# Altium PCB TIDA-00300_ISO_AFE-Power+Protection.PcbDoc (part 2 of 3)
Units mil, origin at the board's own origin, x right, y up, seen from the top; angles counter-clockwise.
Board outline 3622.05 x 2204.8 mil, 4 copper layers (Top Layer, GND Layer, PWR Layer, Bottom Layer), stack 63.6 mil thick; 240 components, 107 nets, 584 pads, 225 vias.
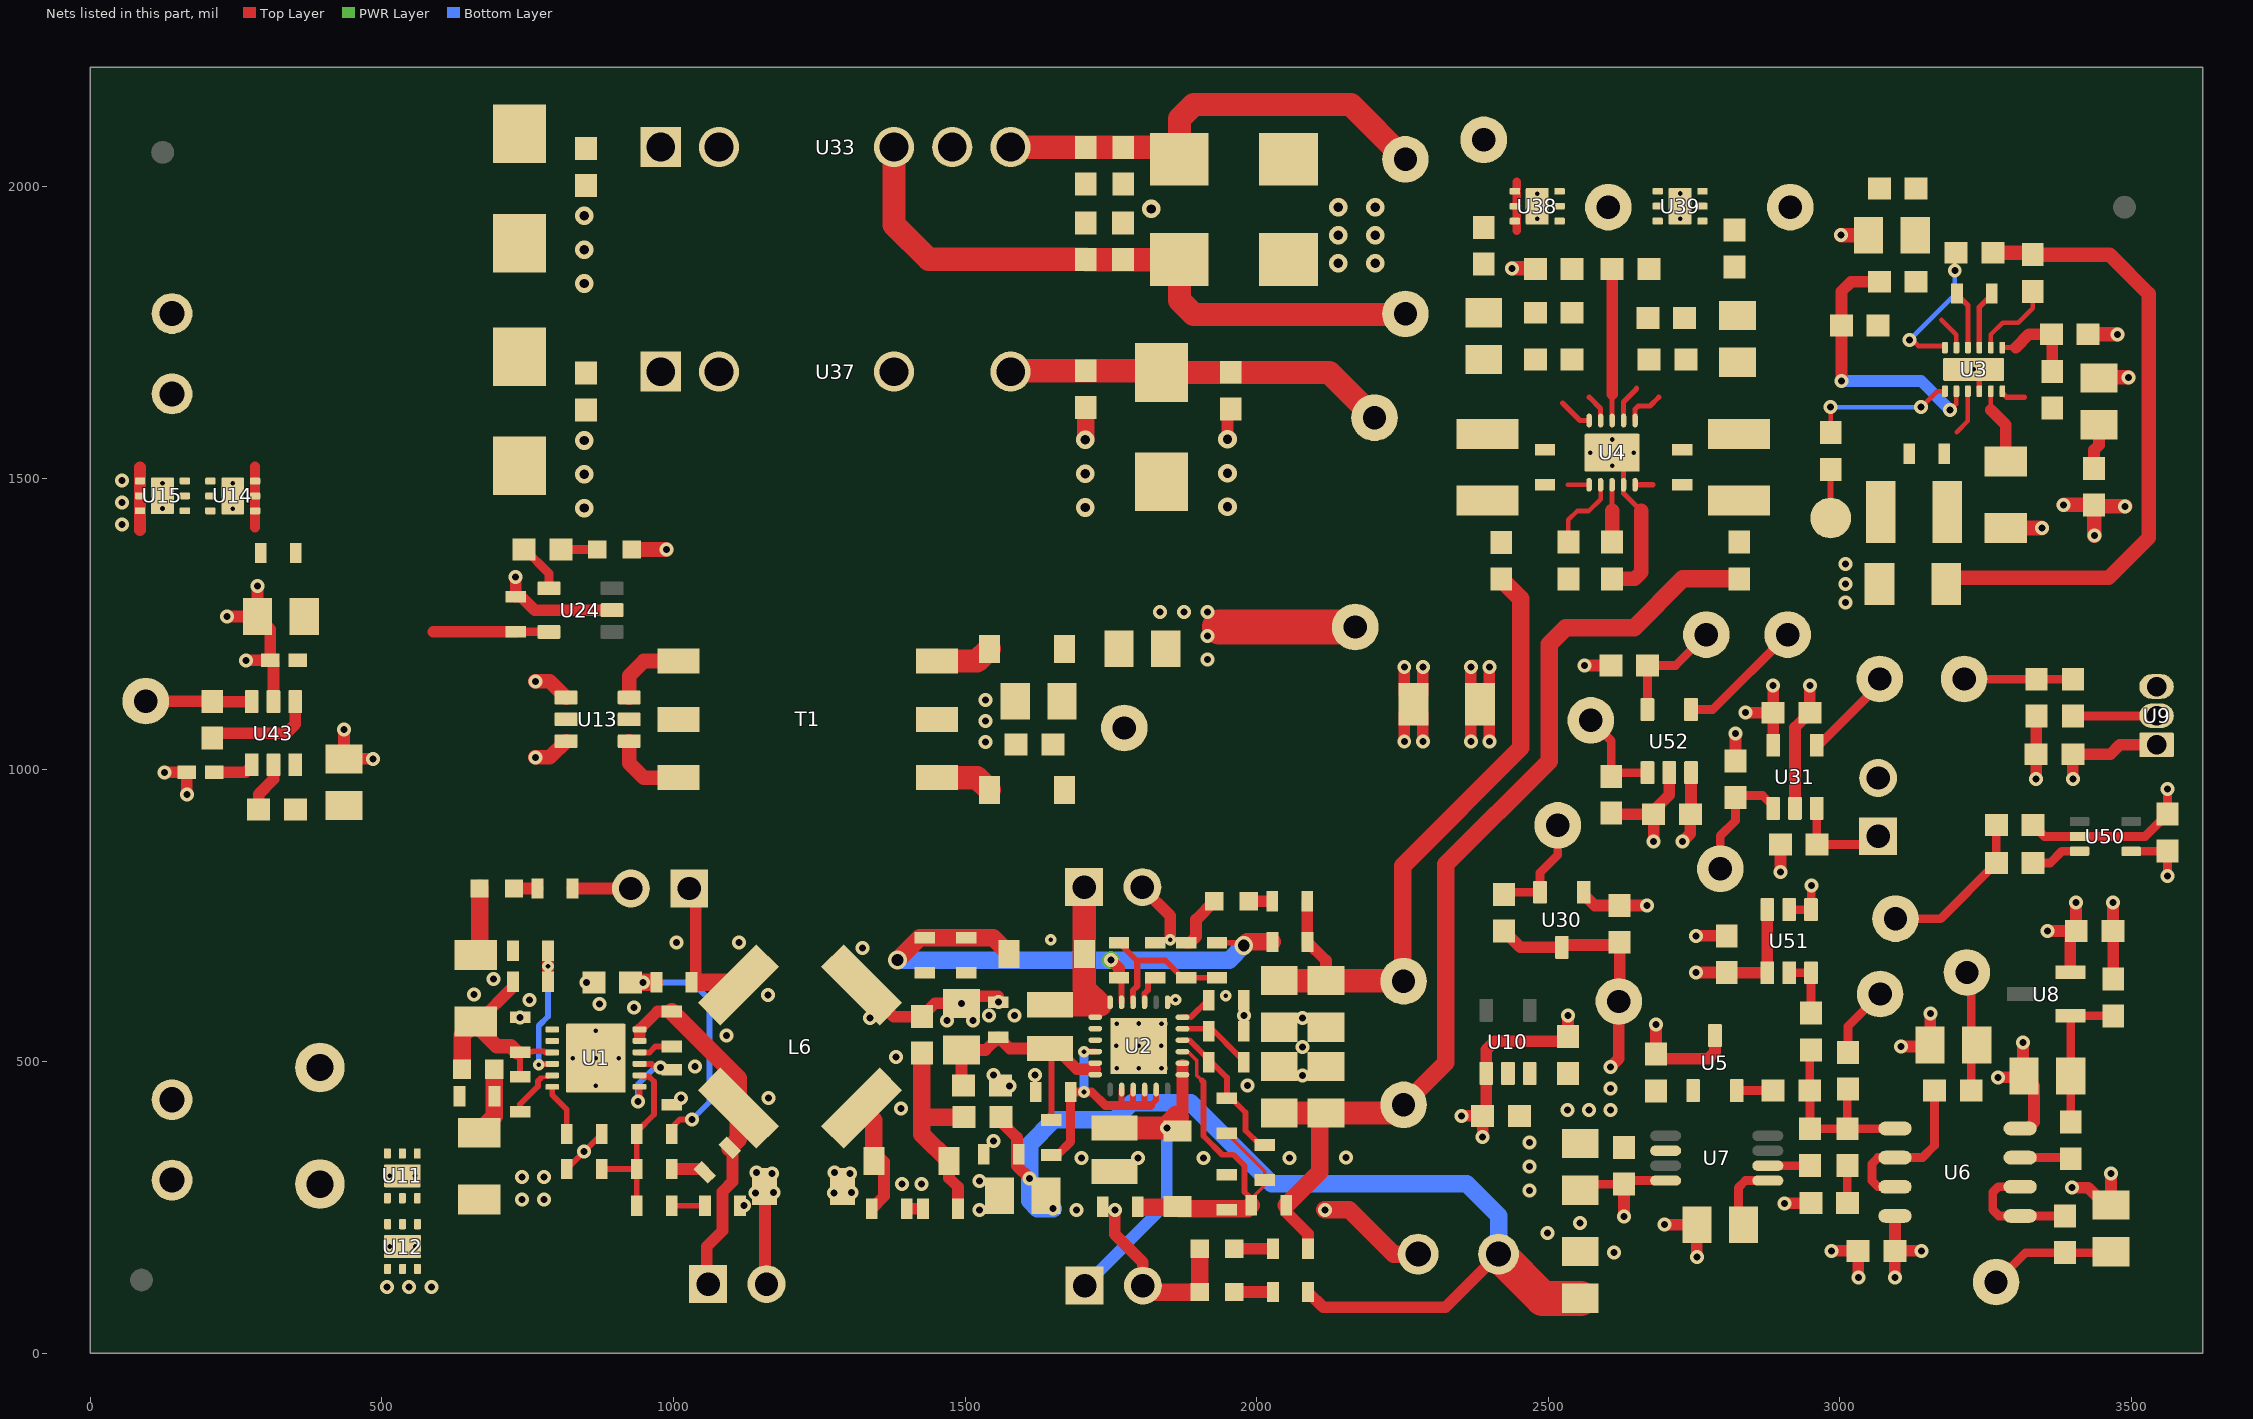
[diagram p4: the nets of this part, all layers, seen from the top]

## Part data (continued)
L4 L5: "Inductor, Wirewound, Ferrite, 10 µH, 0.47 A, 0.435 ohm, SMD", Manufacturer="Wurth Elektronik", Supplier Part Number 1=732-5428-1-ND, Value1="0.435 ohm", Value2=0.47A, ValueDisplayed=10µH
L6: "Coupled inductor, 22 µH, 1.1 A, 0.48 ohm, SMD", Manufacturer="Wurth Elektronik", Supplier Part Number 1=732-2598-1-ND, ValueDisplayed=22µH
Logo1: library part CMP-0074769-1
Logo2: library part Pb-Free
Logo3: library part FCC_disclaimer, "FCC_disclaimer"
Logo4: library part ESD_Susceptible, "ESD Susceptible Symbol"
PT1: library part POLYSWITCH_RXE135, "PTC THERMISTOR C 830-A 160-A 70", Manufacturer=Raychem, Supplier Part Number 1=495-76377-ND
R1: "RES, 1.21 k, 1%, 0.1 W, 0603", Manufacturer=Vishay-Dale, Power_W=0.1, Supplier Part Number 1=541-1.21KHCT-ND, TempCo="100 ppm/C", Tolerance_%=1, Value1=1%, Value2=0.1W, Value_Code=1k21, ValueDisplayed=1.21k
R2 R22 R23 R52: "RES, 1.00, 1%, 0.1 W, 0603", Manufacturer=Vishay-Dale, Power_W=0.1, Supplier Part Number 1=541-3956-1-ND, TempCo="100 ppm/C", Tolerance_%=1, Value1=1%, Value2=0.1W, Value_Code=1R00, ValueDisplayed=1.00
R3: "RES, 113 k, 1%, 0.1 W, 0603", Manufacturer=Vishay-Dale, Power_W=0.1, Supplier Part Number 1=541-113KHCT-ND, TempCo="100 ppm/C", Tolerance_%=1, Value1=1%, Value2=0.1W, Value_Code=113k
R4: "RES, 16.9 k, 1%, 0.1 W, 0603", Manufacturer=Vishay-Dale, Power_W=0.1, Supplier Part Number 1=541-16.9KHCT-ND, TempCo="100 ppm/C", Tolerance_%=1, Value1=1%, Value2=0.1W, Value_Code=16k9, ValueDisplayed=16.9k
R5: "RES, 27.4 k, 1%, 0.1 W, 0603", Manufacturer=Vishay-Dale, Power_W=0.1, Supplier Part Number 1=541-27.4KHCT-ND, TempCo="100 ppm/C", Tolerance_%=1, Value1=1%, Value2=0.1W, Value_Code=27k4, ValueDisplayed=27.4k
R7: "RES, 3.48 k, 1%, 0.1 W, 0603", Manufacturer=Vishay-Dale, Power_W=0.1, Supplier Part Number 1=541-3.48KHCT-ND, TempCo="100 ppm/C", Tolerance_%=1, Value1=1%, Value2=0.1W, Value_Code=3k48, ValueDisplayed=3.48k
R8 R14 R21: "RES, 5.36 k, 1%, 0.1 W, 0603", Manufacturer=Vishay-Dale, Power_W=0.1, Supplier Part Number 1=541-5.36KHCT-ND, TempCo="100 ppm/C", Tolerance_%=1, Value1=1%, Value2=0.1W, Value_Code=5k36, ValueDisplayed=5.36k
R9: "RES, 150, 1%, 0.1 W, 0603", Manufacturer=Vishay-Dale, Power_W=0.1, Supplier Part Number 1=541-150HCT-ND, TempCo="100 ppm/C", Tolerance_%=1, Value1=1%, Value2=0.1W, Value_Code=150R, ValueDisplayed=150
R10 R13: "RES, 2.00 k, 1%, 0.1 W, 0603", Manufacturer=Vishay-Dale, Power_W=0.1, Supplier Part Number 1=541-2.00KHCT-ND, TempCo="100 ppm/C", Tolerance_%=1, Value1=1%, Value2=0.1W, Value_Code=2k00, ValueDisplayed=2.00k
R11: "RES, 42.2, 1%, 0.1 W, 0603", Manufacturer=Vishay-Dale, Power_W=0.1, Supplier Part Number 1=541-42.2HCT-ND, TempCo="100 ppm/C", Tolerance_%=1, Value1=1%, Value2=0.1W, Value_Code=42R2, ValueDisplayed=42.2
R12 R103 R104: "RES, 0, 5%, 0.1 W, 0603", Manufacturer=Panasonic, Power_W=0.1, Supplier Part Number 1=P0.0GCT-ND, TempCo="600 ppm/C", Tolerance_%=5, Value1=5%, Value2=0.1W, Value_Code=0000, ValueDisplayed=0
R15: "RES, 976 k, 1%, 0.1 W, 0603", Manufacturer=Vishay-Dale, Power_W=0.1, Supplier Part Number 1=541-976KHCT-ND, TempCo="100 ppm/C", Tolerance_%=1, Value1=1%, Value2=0.1W, Value_Code=976k
R16: "RES, 86.6 k, 1%, 0.1 W, 0603", Manufacturer=Vishay-Dale, Power_W=0.1, Supplier Part Number 1=541-86.6KHCT-ND, TempCo="100 ppm/C", Tolerance_%=1, Value1=1%, Value2=0.1W, Value_Code=86k6, ValueDisplayed=86.6k
R17: "RES, 105 k, 1%, 0.1 W, 0603", Manufacturer=Vishay-Dale, Power_W=0.1, Supplier Part Number 1=541-105KHCT-ND, TempCo="100 ppm/C", Tolerance_%=1, Value1=1%, Value2=0.1W, Value_Code=105k
R18: "RES, 1.30 M, 1%, 0.1 W, 0603", Manufacturer=Vishay-Dale, Power_W=0.1, Supplier Part Number 1=541-1.30MHCT-ND, TempCo="100 ppm/C", Tolerance_%=1, Value1=1%, Value2=0.1W, Value_Code=1M30, ValueDisplayed=1.30M
R19: "RES, 0, 5%, 0.25 W, 1206", Manufacturer=Vishay-Dale, Power_W=0.25, Supplier Part Number 1=541-0.0ECT-ND, TempCo="200 ppm/C", Tolerance_%=5, Value1=5%, Value2=0.25W, Value_Code=0000, ValueDisplayed=0
R20 R44 R45 R47 R50 R117: "RES, 100, 1%, 0.1 W, 0603", Manufacturer=Vishay-Dale, Power_W=0.1, Supplier Part Number 1=541-100HCT-ND, TempCo="100 ppm/C", Tolerance_%=1, Value1=1%, Value2=0.1W, Value_Code=100R, ValueDisplayed=100
R24 R25 R26 R31 R33 R36 R38 R40 R41: "RES, 0, 5%, 0.1 W, 0603", Manufacturer=Vishay-Dale, Power_W=0.1, Supplier Part Number 1=541-0.0GCT-ND, TempCo="200 ppm/C", Tolerance_%=5, Value1=5%, Value2=0.1W, Value_Code=0000, ValueDisplayed=0
R27 R28 R30 R34: "RES, 249 k, 1%, 0.1 W, 0603", Manufacturer=Vishay-Dale, Power_W=0.1, Supplier Part Number 1=541-249KHCT-ND, TempCo="100 ppm/C", Tolerance_%=1, Value1=1%, Value2=0.1W, Value_Code=249k
R29: library part RNCF0603TKY10K0, "RES, 10.0k ohm, 1%, 0.1W, 0603", Manufacturer="Stackpole Electronics Inc", Power_W=0.063, Supplier Part Number 1=541-10.0KHCT-ND, TempCo="5 ppm/C", Tolerance_%=0.01, Value1=0.01%, Value2=0.063W, Value_Code=10k0
R32 R37: "RES, 75.0 k, 1%, 0.1 W, 0603", Manufacturer=Vishay-Dale, Power_W=0.1, Supplier Part Number 1=541-75.0KHCT-ND, TempCo="100 ppm/C", Tolerance_%=1, Value1=1%, Value2=0.1W, Value_Code=75k0, ValueDisplayed=75.0k
R35: "RES, 27.0 k, 1%, 0.1 W, 0603", Manufacturer="Yageo America", Power_W=0.1, Supplier Part Number 1=311-27.0KHRCT-ND, TempCo="200 ppm/C", Tolerance_%=1, Value1=1%, Value2=0.1W, Value_Code=27k0, ValueDisplayed=27.0k
R39: "RES, 24.0 k, 1%, 0.1 W, 0603", Manufacturer="Yageo America", Power_W=0.1, Supplier Part Number 1=311-24.0KHRCT-ND, TempCo="200 ppm/C", Tolerance_%=1, Value1=1%, Value2=0.1W, Value_Code=24k0, ValueDisplayed=24.0k
R42 R43 R48 R49 R118: "RES, 0 ohm, 5%, 0.1W, 0603", Manufacturer=Vishay-Dale, Power_W=0.1, Supplier Part Number 1=541-0.0GCT-ND, TempCo="200 ppm/C", Tolerance_%=5, Value1=5%, Value2=0.1W, Value_Code=0000
R46: "RES, 2.55 k, 1%, 0.1 W, 0603", Manufacturer=Vishay-Dale, Power_W=0.1, Supplier Part Number 1=541-2.55KHCT-ND, TempCo="100 ppm/C", Tolerance_%=1, Value1=1%, Value2=0.1W, Value_Code=2k55, ValueDisplayed=2.55k
R51: "RES, 0, 5%, 0.25 W, 1206", Manufacturer="Yageo America", Power_W=0.25, Supplier Part Number 1=311-0.0ERCT-ND, TempCo="200 ppm/C", Tolerance_%=5, Value1=5%, Value2=0.25W, Value_Code=0000, ValueDisplayed=0
R75: "RES, 1.00 k, 1%, 0.1 W, AEC-Q200 Grade 0, 0603", Manufacturer=Panasonic, Power_W=0.1, Supplier Part Number 1=P1.00KHCT-ND, TempCo="100 ppm/C", Tolerance_%=1, Value1=1%, Value2=0.1W, Value_Code=1k00, ValueDisplayed=1.00k
R86 R87 R94 R114 R115 R119: "RES, 10.0 k, 1%, 0.1 W, 0603", Manufacturer="Yageo America", Power_W=0.1, Supplier Part Number 1=311-10.0KHRCT-ND, TempCo="200 ppm/C", Tolerance_%=1, Value1=1%, Value2=0.1W, Value_Code=10k0, ValueDisplayed=10.0k
R112 R113: "RES, 0, 5%, 0.125 W, 0805", Manufacturer=Panasonic, Power_W=0.125, Supplier Part Number 1=P0.0ACT-ND, TempCo="600 ppm/C", Tolerance_%=5, Value1=5%, Value2=0.125W, Value_Code=0000, ValueDisplayed=0
R116: "RES, 1.00 k, 1%, 0.1 W, 0603", Manufacturer=Vishay-Dale, Power_W=0.1, Supplier Part Number 1=541-1.00KHCT-ND, TempCo="100 ppm/C", Tolerance_%=1, Value1=1%, Value2=0.1W, Value_Code=1k00, ValueDisplayed=1.00k
T1: library part CMP-0030623-1, "Transformer, 105uH, TH", Manufacturer="Wurth Elektronik", Supplier Part Number 1=1297-1178-1-ND, ValueDisplayed=105uH
TP1 TP2 TP5 TP6 TP24 TP25 TP27 TP29 TP31 TP43 TP44 TP49: "Test Point, Miniature, Red, TH", Color=Red, Manufacturer=Keystone, Supplier Part Number 1=36-5000-ND
TP3: library part PogoPad, "Pad for Pogo Pin Connector"
TP4 TP7 TP9 TP10 TP33 TP38 TP45 TP46 TP47 TP48: "Test Point, Miniature, White, TH", Color=White, Manufacturer=Keystone, Supplier Part Number 1=36-5002-ND
TP32: "Test Point, Miniature, Black, TH", Color=Black, Manufacturer=Keystone, Supplier Part Number 1=36-5001-ND
U1: "Wide Input 65V, 1.5A Synchronous Step-Down DC-DC Converter, DNT0012B", Alternate Manufacturer="Texas Instruments", Alternate PartNumber=LM5160DNTT, Supplier Part Number 1=296-46122-1-ND
U2: "Positive and Negative Output DC-DC Converter, RGE0024B", Alternate Manufacturer="Texas Instruments", Alternate PartNumber=TPS65130RGET, Supplier Part Number 1=296-17080-1-ND
U3: library part LM27762DSSR, "Low-Noise Regulated Switched-Capacitor Voltage Inverter and Positive LDO, DSS0012B", Alternate Manufacturer="Texas Instruments", Supplier Part Number 1=296-44944-1-ND
U4: "Wide-VIN (±33 V), 150-mA, Spilt-Rail Output, Positive and Negative LDO Voltage Regulator with Startup Tracking, DSC0010J", Alternate Manufacturer="Texas Instruments", Supplier Part Number 1=296-47504-1-ND
U5: "2.5 V, 50 ppm / degC, 50 uA Series (Bandgap) Voltage Reference, -40 to 125 degC, 3-pin SOT-23 (DBZ), Green (RoHS & no Sb/Br)", Alternate Manufacturer="Texas Instruments", Alternate PartNumber=Equivalent, Rating=Catalog, Supplier Part Number 1=296-26322-1-ND, Temp Coeff(Max)(ppm/ degree C)=50, Temp Coeff(Typ)(ppm/ degree C)=20
U6: library part CMP-0040811-1, "Precision, Low Noise, Low Quiescent Current Operational Amplifier, 2 to 5.5 V, -40 to 125 degC, 8-pin SOIC (D8), Green (RoHS & no Sb/Br)", Manufacturer="Texas Instruments", Supplier Part Number 1=296-22630-1-ND, Total Supply Voltage(Max)(+5V is 5, +/-5V is 10)=5.5, Total Supply Voltage(Min)(+5V is 5, +/-5V is 10)=2
U7: "Low Noise, Very Low Drift, Precision Voltage Reference, -40 to 125 degC, 8-pin MSOP(DGK), Green (RoHS & no Sb/Br)", Alternate Manufacturer="Texas Instruments", Alternate PartNumber=Equivalent, Rating=Military, Supplier Part Number 1=296-24498-1-ND, Temp Coeff(Max)(ppm/ degree C)=3
U8: "Precision Micropower Shunt Voltage Reference, 3-pin SOT-23, Pb-Free", Manufacturer="Texas Instruments", PackageTopMarking=R2A*XTT, PowerWise=N, Supplier Part Number 1=LM4040AIM3-2.5/NOPBCT-ND
U9: library part CMP-0076506-2, "1.5V-Capable, 10 uA Analog Output Temperature Sensor in SC70 and TO-92, LP0003A (TO-92-3)", Alternate Manufacturer="Texas Instruments", Supplier Part Number 1=LMT84LPM-ND
U10: "Single Output LDO, 150 mA, Fixed 3.3 V Output, 2.5 to 24 V Input, with Ultra-Low IQ, 5-pin SOT-23 (DBV), -40 to 125 degC, Green (RoHS & no Sb/Br)", Alternate Manufacturer="Texas Instruments", Alternate PartNumber=Equivalent, Supplier Part Number 1=296-39285-1-ND
U11: library part CMP-0013424-7, "33-V Precision Surge Protection Clamp, DRV0006A (WSON-6)", Alternate Manufacturer="Texas Instruments", Alternate PartNumber=TVS3300DRVT, Supplier Part Number 1=296-47565-1-ND
U12 U14 U15: library part CMP-0077837-1, "5-V Precision Surge Protection Clamp, DRV0006A (WSON-6)", Alternate Manufacturer="Texas Instruments", Supplier Part Number 1=296-48382-1-ND
U13: "LOW-NOISE 1A TRANSFORMER DRIVERS FOR ISOLATED POWER SUPPLIES, DBV0006A", Alternate Manufacturer="Texas Instruments", Alternate PartNumber=SN6505BDBVT, Supplier Part Number 1=296-47311-1-ND
U24: library part CMP-0067322-1, "Overvoltage/Undervoltage Protection IC in SOT-23-5, DBV0005A (SOT-23-5)", Alternate Manufacturer="Texas Instruments", Alternate PartNumber=TPS2400DBVT, Supplier Part Number 1=296-17744-1-ND
U30: library part CMP-0074269-1, "150-nA, Ultralow Power, Supply Voltage Monitor, DBZ0003A (SOT-23-3)", Alternate Manufacturer="Texas Instruments", Alternate PartNumber=TPS3839E16DBZT, Supplier Part Number 1=296-40757-1-ND
U31: library part CMP-0067355-1, "Voltage Monitor With Watchdog Timer, DBV0005A (SOT-23-5)", Alternate Manufacturer="Texas Instruments", Alternate PartNumber=TPS3828-33DBVT, Supplier Part Number 1=296-32484-2-ND
U33: library part CMP-0030760-1, "Miniature, 1 W, 3 kVDC Isolated DC-DC Converter, -40 to 85 degC, 5-pin Module (EDJ5), Pb-Free (RoHS)", Manufacturer="Texas Instruments", Supplier Part Number 1=296-20641-ND
U37: library part CMP-0030757-1, "Miniature, 1 W, 3 kVDC Isolated DC-DC Converter, -40 to 85 degC, 4-pin Module (EDJ4), Pb-Free (RoHS)", Manufacturer="Texas Instruments", Supplier Part Number 1=296-20638-ND
U38 U39: library part CMP-0077836-1, "14-V Precision Surge Protection Clamp, DRV0006A (WSON-6)", Alternate Manufacturer="Texas Instruments", Supplier Part Number 1=TVS1400DRVR-ND
U43: library part CMP-0077265-1, "5.5-V, 2-A, 80 mohm Low Leakage Load Switch with RCB and Programmable Rise Time, DBV0006A (SOT-23-6)", Alternate Manufacturer="Texas Instruments", Alternate PartNumber=TPS22917DBVT, Supplier Part Number 1=TPS22917DBVR-ND
U50: library part CMP-0013250-1, "TMP235DCK, DCK0005A (SOT-5)", Alternate Manufacturer="Texas Instruments"
U51: library part CMP-0083672-1, "2.5V Low-Drift Low-Power Small-Footprint Series Voltage Reference, DBV0006A (SOT-23-6)", Alternate Manufacturer="Texas Instruments", Operating Temperature Range="-40 to 125 C", Rating=Catalog
U52: library part CMP-0084479-1, "Nano Power, Wide VIN Voltage Detector with Programmable Delay, DBV0005A (SOT-23-5)", Alternate Manufacturer="Texas Instruments"
ZZ1: library part AssemblyNoteLabel
ZZ2 ZZ3 ZZ4: library part AssemblyNote

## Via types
v1: diameter 24, hole 12, Top Layer to Bottom Layer, tented both sides, 165 vias
v2: diameter 19.68, hole 7.87, Top Layer to Bottom Layer, 27 vias
v3: diameter 32, hole 16, Top Layer to Bottom Layer, tented both sides, 19 vias
v4: diameter 20, hole 8, Top Layer to Bottom Layer, tented both sides, 12 vias
v5: diameter 32, hole 20, Top Layer to Bottom Layer, tented both sides, 2 vias

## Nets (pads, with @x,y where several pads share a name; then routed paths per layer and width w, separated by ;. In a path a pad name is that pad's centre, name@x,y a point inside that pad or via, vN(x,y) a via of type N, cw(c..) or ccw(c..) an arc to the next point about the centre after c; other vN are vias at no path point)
+3.3V: C46.1 C47.2 C49.2 C53.1 C54.1 C56.2 C59.1 C99.1 C100.1 C135.2 C137.1 C139.1 R46.1 R86.1 R87.1 R94.1 R119.1 TP49.1 U5.1 U6.8 U7.2 U9.1 U10.3 U30.3 U31.5 U50.4 U51.3 U51.4 U52.2 | length 1692.4
  Top Layer w15: U50.4@3499.52,860.4 3560.94,860.4 C135.2@3561.61,861.08 v1(3561.61,817.99)
  Top Layer w20: R86.1@2424.25,723.5 2452,695.75 U30.3@2523.25,695.75 ; U30.3@2523.25,699.69 2617.44,699.69 C99.1@2622.25,704.5 2622.25,604.24 TP49.1@2621,602.99 2621,504.72 v1(2607,490.72) ; R119.1@2608.06,925.81 2609.86,924.02 C139.1@2680.57,924.02 ; v1@2680.57,877.17 C139.1@2680.57,924.02 ; U52.2@2707.36,995.32 2707.36,956.93 2680.57,930.14 C139.1@2680.57,924.02 ; v1(2753.5,652.5) C137.1@2806,652.5 2806.33,652.17 U51.4@2875.6,652.17 U51.3@2875.6,760.44 ; R87.1@2821,1015.69 v1(2821,1062.62) ; v1(2838.57,1098.19) C100.1@2885.5,1098.19 ; v1(2885.5,1145.12) C100.1@2885.5,1098.19 ; U31.5@2885.6,1038.39 U31.5@2885.6,1042.33 2885.6,1098.1 C100.1@2885.5,1098.19 ; v1(2898.05,825.24) R94.1@2898.05,872.17 ; v1@3094.3,130.42 C47.2@3094.3,175.23 ; U6.8@3094.52,235.23 3094.52,175.45 C47.2@3094.3,175.23 ; v1(3140,174.72) 3139.49,175.23 C47.2@3094.3,175.23 ; v1(3399.5,984.5) C56.2@3399.5,1026.99 3464,1026.99 3480,1042.99 U9.1@3543,1042.99 ; v1(3468.35,772.37) C49.2@3468.35,723.72 3468.85,723.21 R46.1@3468.85,641.21
  other v1: 3094.81,129.92 2533,416.72 2570,416.72 2607,416.72 2607,453.72 2680.57,876.99
+5V_IN: C58.1 L3.1 R19.2 R112.2 R113.2 TP44.1 U10.2 | length 233
  Top Layer w60: 1936,1244.99 TP44.1@2169,1244.99
  other v1: 2612.85,172.39 2499,205.99 2554,222.99 2468,278.72 2468,319.72 2468,360.72 1576,457.99 1549,476.99 1916,1188.99 1916,1229.99 1834,1270.99 1875,1270.99 1916,1270.99 3010,1286.99 3010,1318.99 3010,1352.99
+5V_IN_ISO_DCDC: C115.1 C117.1 R116.2 TP25.1 U37.7 | length 658
  Top Layer w40: U37.7@1578,1682.99 1579.5,1684.49 C117.1@1707,1684.49 1834.01,1684.49 C115.1@1837,1681.5 2124.5,1681.5 TP25.1@2202,1603.99
+12V: R24.2 R25.2 TP29.1 U38.4 U38.5 U38.6 | length 91.8
  Top Layer w15: 2445.94,1924.86 2445.94,1937.73 U38.6@2442.61,1941.06 2445.94,1944.38 2445.94,1963.32 U38.5@2442.61,1966.65 2445.94,1969.97 2445.94,1988.91 U38.4@2442.61,1992.24 2445.94,1995.56 2445.94,2008.44
+14V: C16.1 C17.1 R14.1 R22.2 R26.1 R38.1 TP1.1 | length 1165
  Top Layer w20: R22.2@2086.85,698.72 R14.1@2086.85,774.72 ; R22.2@2087,704.99 2118.85,673.14 C16.1@2118.85,638.72
  Top Layer w30: TP1.1@2250.85,638.72 2250.85,835.84 2453,1037.99 2453,1293.75 R26.1@2419.4,1327.35 ; R38.1@2534.25,1327.35 R38.1@2534.4,1327.5
  Top Layer w40: C17.1@2027.85,638.72 C17.1@2038.85,638.72 C16.1@2118.85,638.72 TP1.1@2250.85,638.72
+15V_IN_ISO_DCDC: C109.1 C111.1 R114.1 TP24.1 U33.7 | length 804.3
  Top Layer w40: U33.7@1578,2067.99 1578.5,2067.49 C111.1@1707,2067.49 R114.1@1771,2067.49 1847,2067.49 C109.1@1867.5,2046.99 1867.5,2116.49 1892,2140.99 2161,2140.99 TP24.1@2255,2046.99
-12V: R40.2 R41.2 TP31.1 U39.1 U39.2 U39.3 U39.7@2726,1966.71 | length 154.5
  Top Layer w25: v1(3383.53,1454.65) R40.2@3435.03,1454.65 ; v1(3436.36,1401.82) R40.2@3436.36,1453.32 ; R40.2@3437.68,1452 v1(3489.18,1452)
  other v2: 2726,1945.06 2726,1988.36
-14V: C25.2 C26.2 R21.2 R23.2 R33.1 TP2.1 | length 1767.5
  Top Layer w20: R23.2@2050.85,253.72 2050.85,241.72 2087.85,204.72 R21.2@2087.85,178.72
  Top Layer w30: R23.2@2050.85,253.72 2107.85,310.72 C26.2@2107.85,411.72 ; TP2.1@2237.85,411.72 TP2.1@2251.85,425.72 2324.34,498.21 2324.34,838.33 2501.28,1015.27 2501.28,1215.69 2529.58,1243.99 2647,1243.99 2730.5,1327.5 R33.1@2827.4,1327.5
  Top Layer w40: C25.2@2027.85,411.72 C25.2@2038.85,411.72 2107.85,411.72 C26.2@2118.85,411.72 TP2.1@2237.85,411.72
-15V_IN_ISO_DCDC: C112.2 C113.2 R115.2 TP27.1 U33.5 | length 1114.9
  Top Layer w40: U33.5@1378,2067.99 1378,1934.99 1437.5,1875.5 1707,1875.5 1707.5,1874.99 C112.2@1867.5,1874.99 1867.5,1805.5 1892,1780.99 2254,1780.99 TP27.1@2255,1781.99
AGND: C9.1 C32.1 C33.2 C34.2 C35.2 C37.2 C39.2 C41.2 C42.2 C43.1 C44.2 C45.2 C46.2 C47.1 C48.2 C49.1 C50.2 C51.2 C52.2 C53.2 C54.2 C55.2 C56.1 C57.1 C58.2 C59.2 C99.2 C100.2 C135.1 C136.1 C137.2 C138.1 C139.2 J15.2 R32.1 R35.1 R37.1 R51.1 TP32.1 U3.4 U3.13@3229.36,1686.82 U4.4 U4.11 U5.3 U6.4 U7.4 U8.2 U9.3 U10.1 U30.1 U31.2 U38.1 U38.2 U38.3 U38.7@2481,1966.65 U39.4 U39.5 U39.6 U50.2 U51.1 U51.2 U52.3 | length 3524.5
  Top Layer w8: v2(3229.36,1686.82) U3.13@3239.2,1676.98
  Top Layer w9: U4.11@2609.4,1543.99 2629.09,1524.31 U4.4@2629.09,1488.88 2629.09,1474.31 2659.4,1443.99 ; U3.4@3239.2,1649.42 U3.13@3239.2,1676.98
  Top Layer w15: C53.2@2554.81,279.23 2565.31,289.73 C54.2@2629.81,289.73 ; C54.2@2635.92,295.84 U7.4@2701.21,295.84 ; U51.2@2913,760.44 U51.1@2950.4,760.44 2951,761.03 v1(2951,801.99) ; C136.1@3331.25,905.38 3350.64,885.99 U50.2@3410.93,885.99 3523.54,885.99 C135.1@3561.61,924.07 v1(3561.61,967.61)
  Top Layer w20: v1(2351,406.72) C58.2@2387.38,406.69 ; v1(2367.17,1048.72) 2367.17,1096.8 R51.1@2383.09,1112.72 ; v1(2367.17,1176.72) 2367.17,1128.63 R51.1@2383.09,1112.72 ; v1(2387.38,370.34) C58.2@2387.38,406.69 ; C58.2@2393.47,412.79 U10.1@2393.47,479.56 2393.47,520.19 2408,534.72 2525.9,534.72 C59.2@2533.87,542.69 v1(2533.9,579.07) ; v1(2399,1048.72) 2399,1096.8 R51.1@2383.09,1112.72 ; v1(2399,1176.72) 2399,1128.63 R51.1@2383.09,1112.72 ; U30.1@2560.65,786.3 2579.46,767.49 C99.2@2622.25,767.49 v1(2669.04,767.49) ; v1(2562,1178.99) C138.1@2607.5,1178.99 ; v1(2629.81,234.42) C54.2@2629.81,289.73 ; v1(2684.81,563.53) C46.2@2684.81,512.72 2692.81,504.72 2774,504.72 2785.81,516.53 U5.3@2785.81,544.47 ; v1(2699.49,220.23) C48.2@2754.81,220.23 v1(2754.81,164.91) ; v1(2729.85,876.99) 2743.56,890.7 C139.2@2743.56,924.02 2744.76,925.21 U52.3@2744.76,995.32 ; v1(2753.5,715.49) C137.2@2806,715.49 ; v1@2905.51,257.23 C55.2@2950.31,257.23 ; U31.2@2923,938 2923.06,938.06 2923.06,1072.76 C100.2@2948.5,1098.19 v1(2948.5,1145.12) ; v1@2986.51,175.23 C47.1@3031.31,175.23 v1@3031.31,130.42 ; v1(3105,525.72) 3152.3,525.72 C52.2@3154.81,528.23 3155,528.42 v1(3155,582.72) ; v1(3271,472.72) 3313.3,472.72 C51.2@3315.3,474.72 ; U6.4@3309.09,385.23 3322.51,385.23 3333,395.72 3333,458.03 C51.2@3315.81,475.23 3314,477.03 v1(3314,532.72) ; v1(3336.5,984.5) C56.1@3336.5,1026.99 3336.5,1092 C57.1@3337,1092.5 ; v1(3355.69,723.72) C49.1@3404.35,723.72 ; U8.2@3395.19,653.12 3395.19,713.55 C49.1@3405.35,723.72 ; v1(3398,283.72) 3426,283.72 3456,253.72 C50.2@3464.85,253.72 v1(3464.85,307.57) ; C49.1@3404.85,724.22 v1(3404.85,772.88)
  Top Layer w25: v1(2438,1859.99) 2476.91,1859.99 R35.1@2477.91,1858.99 ; C42.2@2609.4,1327.5 2647.91,1327.5 2659.4,1338.99 2659.4,1443.99 ; v1(3002.19,1916.98) C34.2@3049.2,1916.98 ; C45.2@3284.2,1414.89 v1(3346.36,1414.89) ; R37.1@3425.7,1746.98 v1(3475.7,1746.98) ; C39.2@3444.2,1671.98 3445.44,1673.22 v1(3494.83,1673.22)
  other v1: 3031.82,129.92 2986,174.72 2905,256.72
  other v2: 2609.4,1521.36 2572,1543.99 2646.8,1543.99 2609.4,1566.63 2481,1944.99 2481,1988.3
EXT_5V: C84.1 C108.1 C110.1 C114.1 C116.1 C121.1 R104.2 T1.2 U13.2 U13.5 U24.5 U33.1 U37.1 U43.6 | length 198.4
  Top Layer w15: C84.1@729.42,1236.99 785.88,1236.99 U24.5@786.28,1236.59
  Top Layer w20: 588,1236.99 C84.1@729.42,1236.99
GND: C1.2 C3.2 C4.2 C5.2 C10.2 C11.2 C12.2 C13.2 C60.2 C84.2 C108.2 C110.2 C114.2 C116.2 C120.2 C121.2 C122.2 D5.2 D11.2 J1.2 J2.2 J4.2 R10.1 R13.1 U1.1 U1.2 U1.13 U12.4 U12.5 U12.6 U13.4 U13.6 U15.4 U15.5 U15.6 U24.2 U33.2 U37.2 U43.2 | length 1347.1
  Top Layer w10: R13.1@816.85,315.72 v1(846.85,345.72) C10.2@876.85,375.72
  Top Layer w20: 85.23,1411.22 U15.6@85.23,1444.4 U15.5@85.23,1469.99 U15.4@85.23,1495.58 85.23,1519.22 ; v1(127,995.99) C122.2@165.38,995.99 v1(165.38,957.62) ; v1(234.15,1263.14) C60.2@286.72,1263.14 ; v1(267,1187.99) C120.2@308.38,1187.99 ; v1(286.72,1315.72) C60.2@286.72,1263.14 ; U43.2@314,1117.13 314,1182.37 C120.2@308.38,1187.99 ; v1(435,1068.99) C121.2@435,1018.99 v1(485,1018.99) ; v1@729.42,1330.58 C84.2@729.42,1296.99 739.1,1296.99 762.1,1273.99 U24.2@894.55,1273.99 ; C1.2@1155.92,285.72 1156.85,284.79 J2.2@1156.85,115.72 ; C60.2@286.72,1263.14 308.38,1241.49 C120.2@308.38,1187.99
  Top Layer w25: v1(763,1021.44) 787.84,1021.44 U13.6@815.72,1049.32 ; v1(763,1151.99) 787.84,1151.99 U13.4@815.72,1124.12 ; D11.2@928.53,1377.99 v1(987.58,1377.99)
  Top Layer w30: C4.2@667.32,689.28 D5.2@667.32,796.72
  other v1: 508.78,113.32 546.78,113.32 584.78,113.32 1120.85,252.72 740,263.72 778,263.72 1140.92,274.72 1171,274.99 740,301.72 778,301.72 1169,307.99 1142,309.99 1013,436.99 1162.85,437.72 1036.85,491.72 1090.85,544.72 736.85,575.72 932,592.99 872.85,598.72 752.85,605.72 1161.85,613.72 657.85,614.72 850.85,635.72 690.85,641.72 1004.85,703.72 1111.85,703.72 729,1330.99 54.22,1420.5 54.22,1458.5 54.22,1496.5
  other v2: 866.85,458.47 827.48,505.72 866.85,505.72 906.22,505.72 866.85,552.96
  other v3: 847,1448.99 847,1506.99 847,1564.99 847,1833.99 847,1891.99 847,1949.99
GND_ISO: C1.1 C6.2 C7.2 C15.2 C16.2 C17.2 C18.2 C19.2 C21.2 C22.2 C23.2 C25.1 C26.1 C27.1 C28.1 C29.2 C30.2 C31.2 C61.2 C62.1 C109.2 C111.2 C112.1 C113.1 C115.2 C117.2 D1.2 D6.2 D10.1 J6.1 J8.2 J12.2 L5.2 L6.1 R16.1 R51.2 R114.2 R115.1 R116.1 T1.5 U2.2 U2.3 U2.19 U2.25 U33.6 U37.5 | length 1387.2
  Top Layer w20: L6.1@1322.64,631.51 1377.43,576.72 1425.35,576.72 C6.2@1425.85,577.21 1448.35,599.72 v1(1493.85,599.72) 1505.85,611.72 v1@1556.85,611.72 ; v1(1756.85,245.72) 1756.85,203.72 1804.85,155.72 J12.2@1804.85,115.72 ; J8.2@1804.85,796.72 1851.85,749.72 v4(1851.85,708.72) ; R16.1@1878.85,703.72 1885.52,703.72 1896,714.19 1896,743.4 D6.2@1927.32,774.72 ; v3(1950,1566.99) 1950,1613.53 R116.1@1955.39,1618.91 ; v1(2253,1048.72) 2253,1096.8 R51.2@2268.91,1112.72 ; v1(2253,1176.72) 2253,1128.63 R51.2@2268.91,1112.72 ; v1(2284.83,1048.72) 2284.83,1096.8 R51.2@2268.91,1112.72 ; v1(2284.83,1176.72) 2284.83,1128.63 R51.2@2268.91,1112.72
  Top Layer w30: v3(1706,1565.99) 1707,1566.99 C117.2@1707,1621.5 ; J12.2@1804.85,115.72 1815.85,104.72 D1.2@1902.32,104.72 1902.8,104.72 1902.32,105.19 D10.1@1902.32,178.72 ; v3(1950,1566.99) v3@1951,1567.99 ; v1(2116.85,245.72) 2158.85,245.72 2234.85,169.72 J6.1@2276.85,169.72 ; v3(2140,1964.99) v3@2141,1965.99
  other v1: 1524.85,245.72 1690.85,245.72 1274.78,274.72 1304.86,274.99 1391.85,289.72 1425,289.99 1525,294.72 1302.86,307.99 1275.86,309.99 1699.85,334.72 1796.85,334.72 1908.85,334.72 2055.85,334.72 2153,334.99 1549.01,363.45 1389.85,419.72 1983.85,458.72 2078.85,475.72 1619.85,476.72 1381.85,507.72 2078.85,524.72 1468.85,570.72 1513.85,570.72 1336.85,574.72 2078.85,574.72 1540.85,578.72 1584.85,578.72 1977.85,578.72 1556.85,601.72 1323.85,694.72 1535,1047.72 1535,1083.72 1535,1119.72
  other v2: 1797.85,488.33 1759.46,526.72 1797.85,526.72 1836.24,526.72 1797.85,565.1
  other v3: 1706,1449.99 1950,1450.99 1706,1507.99 1950,1508.99 2140,1868.99 2203,1868.99 2140,1916.99 2203,1916.99 1819,1961.99 2203,1964.99
  other v4: 1759.85,488.72 1836.85,488.72 1759.93,564.64 1836.85,564.72 1860.85,605.72 1946.85,612.72 1646.85,708.72
NetC2_1: C2.1 U1.10 | length 59.4
  Top Layer w10: U1.10@941.65,515.56 958.69,515.56 968.85,525.72 C2.1@996.85,525.72
NetC2_2: C2.2 J2.1 L6.3 R5.1 U1.11 U1.12 | length 626.9
  Top Layer w20: U1.11@941.85,539.72 U1.12@941.65,554.93 972.44,585.72 C2.2@996.85,585.72 ; J2.1@1056.85,115.72 1056.85,182.72 1084,209.87 1084,276.87 1100.98,293.84 1100.98,347.44 R5.1@1096.21,352.21
  Top Layer w30: C2.2@996.85,585.72 1111.06,471.51 L6.3@1111.06,419.93 1111.06,367.06 R5.1@1096.21,352.21
NetC3_1: C3.1 L1.1 R2.1 | length 117.2
  Top Layer w30: C3.1@666.85,377.8 666.85,379.72 692.85,405.72 R2.1@692.85,440.72 L1.1@692.85,484.28
NetC4_1: C4.1 C5.1 L1.2 R3.1 R4.2 U1.3 | length 402.3
  Top Layer w10: R3.1@736.85,473.72 736.85,512.07 741.38,516.59 758.38,516.59 759.23,517.45 778.47,517.45 780.36,515.56 U1.3@792.05,515.56
  Top Layer w20: C4.1@637.29,545.07 C4.1@637.29,570.43 ; C4.1@660.85,568.63 665.52,568.63 724.85,627.97 R4.2@724.85,636.72
  Top Layer w25: C4.1@659.85,563.32 696.85,526.32 720.92,526.32 C5.1@731.53,515.72
  Top Layer w30: L1.2@637.29,486.72 637.29,545.07 C4.1@660.85,568.63
NetC6_1: C6.1 C14.2 D2.1 L2.1 | length 365.1
  Top Layer w20: D2.1@1472.32,328.67 1472.32,300.25 1487.85,284.72 C14.2@1487.85,247.72
  Top Layer w30: C6.1@1425.85,514.22 1425.85,405.99 ; D2.1@1472.23,328.76 D2.1@1472.32,328.67 ; D2.1@1472.47,328.99 1425.85,375.61 1425.85,405.99 ; L2.1@1498.35,404.72 1427.13,404.72 1425.85,405.99
NetC7_1: C7.1 C15.1 J6.2 L2.2 R1.1 R112.1 | length 1796.2
  Top Layer w20: L2.2@1560.35,405.72 L2.2@1561.35,404.72 1561.35,397.22 1588.85,369.72 1588.85,321.5 v1(1610.63,299.72) ; R1.1@2087.85,104.72 2113.85,78.72 2323.65,78.72 J6.2@2414.65,169.72
  Top Layer w60: J6.2@2414.65,169.72 2490.37,93.99 R112.1@2555,93.99
  Bottom Layer w30: v1(1651,247.72) 1623.77,247.72 1610.63,260.86 v1(1610.63,299.72) 1610.63,358.37 1652.26,399.99 1757,399.99 1786,428.99 1887.17,428.99 2026.17,289.99 2360,289.99 2414.65,235.35 J6.2@2414.65,169.72
NetC8_1: C8.1 R5.2 | length 59.4
  Top Layer w20: C8.1@996.85,315.72 1047.85,315.72 R5.2@1053.79,309.78
NetC8_2: C8.2 R7.1 R11.2 R13.2 U1.8 | length 311.6
  Top Layer w10: R13.2@876.85,315.72 C8.2@936.85,315.72 ; R11.2@936.85,255.72 C8.2@936.85,315.72 ; U1.8@941.65,476.19 947.98,476.19 947.98,475.41 949.01,474.38 957.57,474.38 966.34,465.61 966.34,409.21 936.85,379.72 R7.1@936.85,375.72 C8.2@936.85,315.72
NetC9_2: C9.2 C33.1 R19.1 R31.1 R36.1 U3.3 | length 1173.8
  Top Layer w8: 3200.2,1578.98 3219.52,1598.29 U3.3@3219.52,1649.42
  Top Layer w20: R36.1@3327.19,1886.98 R36.1@3330.7,1883.47
  Top Layer w25: R19.1@3182.36,1318.82 3192.76,1329.22 3460.7,1329.22 3529.98,1398.5 3529.98,1816.07 3462.58,1883.47 R36.1@3330.7,1883.47 ; R31.1@3262.19,1886.98 R36.1@3327.19,1886.98
NetC10_1: C10.1 U1.6 | length 91.1
  Top Layer w10: U1.6@792.05,456.51 792.05,442.52 816.85,417.72 C10.1@816.85,375.72
NetC11_1: C11.1 U1.7 U1.9 | length 174.8
  Top Layer w10: v1@941.65,434.52 U1.7@941.65,456.51 ; U1.9@941.65,495.88 962.69,495.88 972.57,485.99 976.57,489.99 v1(978,489.99) 992.57,489.99 C11.1@996.85,485.72 C11.1@1006.63,485.72
  Bottom Layer w10: v1(938.85,431.72) 938.85,460.72 968.13,489.99 v1(978,489.99)
NetC12_1: C12.1 R11.1 | length 57.1
  Top Layer w10: R11.1@996.85,252.72 C12.1@1054,252.72
NetC13_1: C13.1 R7.2 R12.1 | length 437.8
  Top Layer w10: R7.2@996.85,375.72 996.85,386.72 1010.85,400.72 v1(1031.85,400.72)
  Top Layer w30: C13.1@924.85,635.72 C13.1@926.35,635.72 v1(947.85,635.72) R12.1@966.85,635.72
  Bottom Layer w10: v1(947.85,635.72) 1032.03,635.72 1061.85,605.9 1061.85,430.72 v1(1031.85,400.72)
NetC14_1: C14.1 R9.1 | length 28
  Top Layer w20: R9.1@1399.85,247.72 C14.1@1427.85,247.72
NetC18_1: C18.1 C19.1 C20.1 D7.1 R15.2 R22.1 U2.23 | length 999.9
  Top Layer w10: U2.23@1768.32,601.52 C20.1@1768.32,643.19 ; R15.2@1931.85,703.72 1973.28,703.72 v5(1978,698.99)
  Top Layer w20: v1(1750.17,673.72) 1763.85,660.04 C20.1@1763.85,643.72
  Top Layer w30: v5(1384,673.99) 1422,711.99 C18.1@1430.85,711.99 C19.1@1502,711.99 1548.11,711.99 D7.1@1575.38,684.72 ; v5(1978,698.99) 1984,704.99 R22.1@2027,704.99
  PWR Layer w30: v1@1749.89,673.99 v1(1750.17,673.72)
  Bottom Layer w30: v5(1384,673.99) v1@1749.89,673.99 ; v1(1750.17,673.72) 1952.72,673.72 v5(1978,698.99)
NetC20_2: C20.2 R15.1 R16.2 U2.22 | length 310.5
  Top Layer w10: C20.2@1763.85,703.72 1794.22,673.34 1794.22,628.39 ; U2.22@1788.01,601.52 1788.01,621.72 ; 1788.01,622.17 1794.22,628.39 ; R15.1@1931.85,643.72 R16.2@1878.85,643.72 1872.85,643.72 1843.57,672.99 1795.48,672.99 1795.48,629.64 1794.22,628.39
NetC21_1: C21.1 R17.2 U2.17 | length 120
  Top Layer w10: U2.17@1872.65,556.25 1911.32,556.25 C21.1@1915.85,551.72 ; C21.1@1919.85,559.04 R17.2@1972.85,506.04
NetC22_1: C22.1 C23.1 L3.2 L4.1 R20.2 U2.5 U2.6 | length 443.9
  Top Layer w10: R20.2@1647.85,399.72 L4.1@1647.85,520.32
  Top Layer w20: L3.2@1497.35,458.72 1493.85,462.22 C22.1@1493.85,519.72 1534.85,519.72 C23.1@1556.85,541.72 1576.25,522.32 L4.1@1645.85,522.32 1656.25,522.32 1691.85,486.72 1722.85,486.72
NetC24_1: C24.1 R17.1 R18.2 U2.16 | length 258.9
  Top Layer w10: U2.16@1872.65,536.56 1884.94,536.56 1897.34,524.16 1897.34,524.1 1948.85,472.59 C24.1@1948.85,436.72 1956.85,436.72 1980.85,412.72 1980.85,381.72 R18.2@2005.85,356.72 ; R18.2@2001.85,356.72 R18.2@2005.85,356.72 ; R18.2@2013.85,356.72 R18.2@2005.85,356.72
NetC24_2: C24.2 C27.2 C28.2 D8.2 R18.1 R23.1 U2.15 | length 672.3
  Top Layer w6: U2.15@1872.65,516.88 1882.11,516.88 1896.85,502.14 1896.85,476.72 1905.85,467.72 ; C24.2@1948.85,376.72 2013.85,311.72 R18.1@2013.85,296.72 2013.85,287.72 1990.85,264.72 R23.1@1990.85,253.72
  Top Layer w10: 1905.85,467.72 1908.72,464.84 1908.72,372.27 1941,339.99 1960.28,339.99 1979.22,321.05 1979.22,276.34 R23.1@1990.85,264.72
  Top Layer w30: C28.2@1800.85,249.72 1862.19,249.72 D8.2@1864,251.53 1867.86,247.67 1984.8,247.67 R23.1@1990.85,253.72
NetC29_1: C29.1 R20.1 U2.4 U2.8 U2.9 U2.10 U2.11 | length 474.8
  Top Layer w10: v4(1703.85,516.72) 1704.01,516.88 U2.4@1723.05,516.88 ; 1768.32,425.2 U2.8@1768.32,451.92 ; 1788.01,424.89 U2.9@1788.01,451.91 ; 1807.69,424.89 U2.10@1807.69,451.91 ; 1818.35,424.73 1827.38,433.76 U2.11@1827.38,451.92
  Top Layer w15: R20.1@1647.85,339.72 1658.35,339.72 1680.85,362.22 C29.1@1680.85,447.72 v4(1703.85,447.72) 1717.32,447.72 1740.31,424.73 1818.35,424.73
  Bottom Layer w15: v4(1703.85,447.72) v4(1703.85,516.72)
NetC30_1: C30.1 U2.18 | length 55.1
  Top Layer w10: U2.18@1872.65,575.93 1887.06,575.93 C30.1@1915.85,604.72
NetC31_1: C31.1 U2.21 | length 48.1
  Top Layer w10: U2.21@1807.69,601.52 1807.69,616.58 1813.35,622.23 1813.35,635.22 C31.1@1821.85,643.72
NetC32_2: C32.2 C35.1 R26.2 U4.1 | length 36.6
  Top Layer w8: 2533.4,1488.88 U4.1@2570.03,1488.88
NetC34_1: C34.1 R24.1 R27.2 U3.11 | length 58.4
  Top Layer w8: 3174.2,1771.98 3199.83,1746.35 U3.11@3199.83,1724.22
NetC36_1: C36.1 C37.1 R25.1 R28.2 U4.10 | length 58
  Top Layer w9: 2524.4,1628.99 2554.28,1599.11 U4.10@2570.03,1599.11
NetC36_2: C36.2 R28.1 R35.2 U4.9 | length 47.9
  Top Layer w9: 2570.4,1638.99 2589.72,1619.68 U4.9@2589.72,1599.11
NetC38_1: C38.1 U3.9 | length 102.3
  Top Layer w9: U3.9@3239.2,1724.22 3239.2,1793.98 C38.1@3262.19,1816.98
NetC38_2: C38.2 U3.10 | length 101.2
  Top Layer w9: C38.2@3199.2,1816.98 3219.52,1796.66 U3.10@3219.52,1724.22
NetC39_1: C39.1 R30.2 R40.1 U3.6 | length 128.5
  Top Layer w9: U3.6@3278.57,1649.42 3278.57,1646.1 3285.7,1638.98 3316.7,1638.98
  Top Layer w20: R30.2@3360.26,1624.42 R30.2@3364.2,1620.48 ; R40.1@3435.7,1516.98 3435.7,1548.47 3444.2,1556.98 C39.1@3444.2,1591.98
NetC40_1: C40.1 C41.1 R34.2 R41.1 U4.6 | length 68.4
  Top Layer w9: U4.6@2648.77,1599.11 2648.77,1618.36 2654.4,1623.99 2674.4,1623.99 2689.4,1638.99
NetC40_2: C40.2 R34.1 R39.2 U4.7 | length 65.1
  Top Layer w9: U4.7@2629.09,1599.11 2629.09,1630.68 2651.4,1652.99 2651.4,1654.99
NetC42_1: C42.1 U4.3 | length 98.4
  Top Layer w9: 2609.4,1443.99 U4.3@2609.4,1488.88
  Top Layer w25: C42.1@2609.4,1390.49 2609.4,1443.99
NetC43_2: C43.2 C44.1 R33.2 U4.5 | length 30.5
  Top Layer w9: U4.5@2648.77,1488.88 2679.28,1488.88
NetC45_1: C45.1 U3.5 | length 130.8
  Top Layer w8: 3258.89,1617.29 U3.5@3258.89,1649.42
  Top Layer w20: 3258.89,1617.29 3284.2,1591.98 C45.1@3284.2,1529.06
NetC48_1: C48.1 U7.5 | length 122.6
  Top Layer w15: C48.1@2834.81,220.23 2826,229.03 2826,283.72 2838.12,295.84 U7.5@2876.41,295.84
NetC51_1: C51.1 R46.2 R47.1 U8.1 | length 256
  Top Layer w15: R47.1@3395.81,396.23 C51.1@3395.81,475.23 3395.81,577.7 U8.1@3395.19,578.32 3468.76,578.32 R46.2@3468.85,578.22
NetC55_1: C55.1 R49.2 | length 64.7
  Top Layer w15: R49.2@3012.81,321.73 3012.81,257.72 C55.1@3013.3,257.23
NetC60_1: C60.1 C120.1 R52.1 R103.2 U43.1 | length 191
  Top Layer w20: R103.2@209,1054.5 217.5,1062.99 336,1062.99 351.4,1078.4 U43.1@351.4,1117.13
NetC61_1: C61.1 C62.2 D3.1 D9.1 R113.1 TP43.1
NetC122_1: C122.1 U43.4 | length 70.6
  Top Layer w20: C122.1@212.62,995.99 266,995.99 276.6,1006.59 U43.4@276.6,1008.86
NetC138_2: C138.2 TP47.1 U52.5 | length 198.1
  Top Layer w15: U52.5@2669.95,1103.59 2669.95,1178.45 C138.2@2670.5,1178.99 2718,1178.99 TP47.1@2771,1231.99
NetD1_1: D1.1 R1.2 | length 66
  Top Layer w20: D1.1@1961.85,104.72 R1.2@2027.85,104.72
NetD2_2: D2.2 L6.4 R9.2 | length 196.7
  Top Layer w20: R9.2@1339.85,247.72 1360.85,268.72 1360.85,328.25 D2.2@1343.38,345.72
  Top Layer w30: L6.4@1322.64,419.93 1343.38,399.19 D2.2@1343.38,345.72
NetD3_2: D3.2 T1.6 | length 98.7
  Top Layer w40: T1.6@1451.37,1186.72 1520.38,1186.72 D3.2@1541.38,1207.72
NetD5_1: D5.1 R8.1 | length 40.5
  Top Layer w20: D5.1@726.38,796.72 R8.1@766.85,796.72
NetD6_1: D6.1 R14.2 | length 40.5
  Top Layer w20: D6.1@1986.38,774.72 R14.2@2026.85,774.72
NetD7_2: D7.2 J8.1 L4.2 U2.1 U2.24 | length 297.6
  Top Layer w40: L4.2@1645.85,597.12 1732.12,597.12 1704.32,624.92 D7.2@1704.32,684.72 1704.32,796.19 J8.1@1704.85,796.72
NetD8_1: D8.1 J12.1 L5.1 U2.13 U2.14 | length 538
  Top Layer w20: 1863.85,404.19 1872.65,412.99 U2.13@1872.65,477.51 U2.14@1872.65,494.28
  Top Layer w40: L5.1@1755.85,386.12 v1(1845.78,386.12) 1863.85,404.19
  Bottom Layer w20: J12.1@1704.85,115.72 1845.78,256.65 v1(1845.78,386.12)
NetD9_2: D9.2 T1.4 | length 98.7
  Top Layer w40: T1.4@1451.37,986.72 1520.38,986.72 D9.2@1541.38,965.72
NetD10_2: D10.2 R21.1 | length 66.5
  Top Layer w20: D10.2@1961.38,178.72 R21.1@2027.85,178.72
NetD11_1: D11.1 R75.2 | length 64.1
  Top Layer w15: R75.2@805.42,1377.99 R75.2@806.91,1377.99 D11.1@869.47,1377.99
NetJ1_1: J1.1 R52.2 U14.4 U14.5 U14.6 | length 105.1
  Top Layer w17: 282.54,1415.46 U14.4@282.54,1444.15 U14.5@282.54,1469.74 U14.6@282.54,1495.33 282.54,1520.53
NetJ4_1: J4.1 PT1.1
NetJ5_1: J5.1 L6.2 R12.2 | length 234.6
  Top Layer w20: J5.1@1026.85,796.72 1037.85,785.72 R12.2@1037.85,635.72
  Top Layer w30: R12.2@1037.85,635.72 L6.2@1106.85,635.72
NetJ5_2: J5.2 R8.2 | length 100
  Top Layer w20: R8.2@826.85,796.72 J5.2@926.85,796.72
NetJ15_1: J15.1 R94.2 U31.3 | length 176.4
  Top Layer w15: U31.3@2960.4,938 U31.3@2960.4,934.06 2960.4,872.81 R94.2@2961.04,872.17 3051.54,872.17 J15.1@3065.54,886.17
NetPT1_2: PT1.2 R2.2 U11.4 U11.5 U11.6
NetR3_2: R3.2 U1.5 | length 94
  Top Layer w6: 771.85,470.72 773.85,472.72 785.13,472.72 788.61,476.19 U1.5@792.05,476.19
  Top Layer w10: R3.2@736.85,413.72 736.85,426.72 767.35,457.22 767.35,466.22 771.85,470.72
NetR4_1: R4.1 R10.2 U1.4 | length 252
  Top Layer w10: v4(768.85,494.58) 775.71,494.58 777.01,495.88 U1.4@792.05,495.88
  Top Layer w20: R4.1@784.85,636.72 v4(784.85,663.22) R10.2@784.85,689.72
  Bottom Layer w10: v4(768.85,494.58) 768.85,561.26 784.85,577.26 v4(784.85,663.22)
NetR27_1: R27.1 R32.2 U3.2 | length 469.4
  Top Layer w8: v1(3189.2,1616.98) 3199.83,1627.61 U3.2@3199.83,1649.42
  Top Layer w20: v1(3002.7,1666.98) R32.2@3002.7,1761.98 3002.7,1820.48 3019.2,1836.98 R27.1@3067.7,1836.98
  Bottom Layer w20: v1(3002.7,1666.98) 3139.2,1666.98 v1(3189.2,1616.98)
NetR29_1: R29.1 TP3.1 | length 83.5
  Top Layer w10: TP3.1@2984.2,1431.98 R29.1@2984.2,1515.48
NetR29_2: R29.2 U3.1 | length 250.8
  Top Layer w8: R29.2@2984.2,1578.47 v1(2984.2,1621.98) ; v1(3139.2,1621.98) 3166.64,1649.42 U3.1@3180.14,1649.42
  Bottom Layer w8: v1(2984.2,1621.98) v1(3139.2,1621.98)
NetR30_1: R30.1 R37.2 U3.7 | length 157.7
  Top Layer w9: U3.7@3278.57,1724.22 3301.44,1724.22
  Top Layer w20: 3301.44,1724.22 3324.2,1746.98 R37.2@3362.7,1746.98 3364.2,1745.48 R30.1@3364.2,1683.47
NetR31_2: R31.2 U3.12 | length 249.4
  Top Layer w8: v1(3119.2,1736.98) 3124.2,1736.98 3134.2,1726.98 3177.39,1726.98 U3.12@3180.14,1724.22 ; v1(3196.98,1856.5) 3196.98,1884.76 R31.2@3199.2,1886.98
  Bottom Layer w8: v1(3119.2,1736.98) 3196.98,1814.76 v1(3196.98,1856.5)
NetR36_2: R36.2 U3.8 | length 141.5
  Top Layer w8: U3.8@3258.89,1724.22 3258.89,1746.66 3279.2,1766.98 3305.7,1766.98 3330.7,1791.98 R36.2@3330.7,1820.48
NetR38_2: R38.2 U4.2 | length 133
  Top Layer w8: R38.2@2534.4,1390.49 2534.4,1428.99 2549.4,1443.99 2569.4,1443.99 2589.72,1464.31 U4.2@2589.72,1488.88
NetR39_1: R39.1 U4.8 | length 259.9
  Top Layer w9: U4.8@2609.4,1599.11 2609.4,1643.99
  Top Layer w20: 2609.4,1643.99 R39.1@2609.4,1858.99
NetR42_1: R42.1 U5.2 | length 62.2
  Top Layer w15: U5.2@2823.21,449.98 2823.45,450.23 R42.1@2885.31,450.23
NetR42_2: R42.2 R43.2 R48.2 R49.1 R118.2 U6.5 | length 350.7
  Top Layer w15: R118.2@2950.31,519.99 2948.3,517.98 R42.2@2948.3,450.23 2948.81,449.72 R48.2@2948.81,384.72 R49.1@3012.81,384.72 ; R43.2@3013.94,452.69 3012.81,451.56 R49.1@3012.81,384.72 ; U6.5@3094.52,385.23 3094.02,384.72 R49.1@3012.81,384.72
NetR43_1: R43.1 TP4.1 | length 122.8
  Top Layer w15: R43.1@3013.94,515.68 3013.94,560.66 TP4.1@3069,615.72
NetR44_1: R44.1 U6.1 U6.2 | length 209.2
  Top Layer w15: U6.2@3309.09,285.23 3271.51,285.23 3262,275.72 3262,245.72 3272.49,235.23 U6.1@3309.09,235.23 R44.1@3385.85,235.21
NetR45_1: R45.1 U6.6 U6.7 | length 287.3
  Top Layer w15: U6.7@3094.52,285.23 3065.49,285.23 3055,295.72 3055,324.72 3065.51,335.23 U6.6@3094.52,335.23 3141.51,335.23 3162.31,356.03 R45.1@3162.31,450.23
NetR47_2: R47.2 U6.3 | length 87.5
  Top Layer w15: U6.3@3309.09,335.23 3393.81,335.23 R47.2@3395.81,333.23
NetR48_1: R48.1 U7.6 | length 72.5
  Top Layer w15: U7.6@2876.41,321.43 2948.51,321.43 R48.1@2948.81,321.73
NetR50_1: R50.1 U9.2 | length 143.2
  Top Layer w15: R50.1@3400,1092.5 3542.5,1092.5 U9.2@3543,1092.99
NetR75_1: R75.1 U24.4 | length 83.5
  Top Layer w15: R75.1@745.42,1377.99 786.28,1337.13 U24.4@786.28,1311.4
NetR86_2: R86.2 TP38.1 U30.2 | length 190.5
  Top Layer w15: R86.2@2424.25,786.49 2428,790.24 U30.2@2485.85,790.24 2485.85,823.84 2516.2,854.19 TP38.1@2516.2,904.99
NetR87_2: R87.2 TP9.1 U31.1 | length 206.4
  Top Layer w15: TP9.1@2795.06,830.59 2795.06,887.1 2821,913.04 R87.2@2821,952.7 2824.47,956.17 2867.43,956.17 U31.1@2885.6,938
NetR103_1: R103.1 TP33.1 U43.3 | length 182
  Top Layer w20: TP33.1@95,1117.99 95.5,1117.49 R103.1@209,1117.49 209.36,1117.13 U43.3@276.6,1117.13
NetR104_1: R104.1 U43.5 | length 80.4
  Top Layer w20: R104.1@288.5,938.99 288.5,958.5 314,983.99 U43.5@314,1008.86
NetR117_1: R117.1 U50.3 | length 88
  Top Layer w15: R117.1@3331.25,840.38 3360.59,840.38 3380.61,860.4 U50.3@3410.93,860.4
NetR118_1: R118.1 U51.5 U51.6 | length 106.6
  Top Layer w15: U51.5@2913,652.17 U51.6@2950.4,652.17 2950.31,652.08 R118.1@2950.31,582.98
NetR119_2: R119.2 TP46.1 U52.1 | length 175.3
  Top Layer w15: TP46.1@2572.96,1084.99 2608.06,1049.89 R119.2@2608.06,988.8 2614.58,995.32 U52.1@2669.95,995.32
NetT1_1: T1.1 U13.3 | length 132.8
  Top Layer w25: U13.3@923.98,1124.12 923.98,1161.7 949,1186.72 T1.1@1008.85,1186.72
NetT1_3: T1.3 U13.1 | length 132.8
  Top Layer w25: U13.1@923.98,1049.32 923.98,1011.73 949,986.72 T1.3@1008.85,986.72
NetTP48_1: TP48.1 U52.4 | length 218.9
  Top Layer w15: U52.4@2744.76,1103.59 2782.09,1103.59 TP48.1@2910.5,1231.99
NetU11_1: U11.1 U11.2 U11.3 U11.7@535,303.99 U12.1 U12.2 U12.3 U12.7@535.28,182.72
  other v2: 513.63,182.72 556.94,182.72 513.35,303.99 556.65,303.99
NetU14_1: U14.1 U14.2 U14.3 U14.7@244.15,1469.74 U15.1 U15.2 U15.3 U15.7@123.61,1469.99
  other v2: 123.61,1448.34 244.15,1448.09 123.61,1491.65 244.15,1491.4
REF_2.5V: C50.1 R44.2 TP5.1 | length 218.5
  Top Layer w15: TP5.1@3267.85,121.72 3318.35,172.22 R44.2@3385.85,172.22 3463.35,172.22 C50.1@3464.85,173.72
REF_2.5V_A: C52.1 R45.2 TP6.1 | length 215.3
  Top Layer w15: TP6.1@3217.85,652.72 3225.3,645.27 C52.1@3225.3,528.72 ; R45.2@3225.3,450.23 C52.1@3225.3,528.72 ; C52.1@3234.81,528.23 3225.79,528.23 C52.1@3225.3,528.72
TEMP_OUT: C57.2 R50.2 TP7.1 | length 187.2
  Top Layer w15: TP7.1@3213,1155.99 3213.5,1155.49 C57.2@3337,1155.49 R50.2@3400,1155.49
TEMP_OUT1: C136.2 R117.2 TP45.1 | length 277.4
  Top Layer w15: TP45.1@3095.39,744.99 3172.87,744.99 R117.2@3268.26,840.38 C136.2@3268.26,905.38
WDI: TP10.1 U31.4 | length 162.4
  Top Layer w15: U31.4@2960.4,1038.39 2960.4,1039.03 3068.54,1147.17 TP10.1@3068.54,1155.99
